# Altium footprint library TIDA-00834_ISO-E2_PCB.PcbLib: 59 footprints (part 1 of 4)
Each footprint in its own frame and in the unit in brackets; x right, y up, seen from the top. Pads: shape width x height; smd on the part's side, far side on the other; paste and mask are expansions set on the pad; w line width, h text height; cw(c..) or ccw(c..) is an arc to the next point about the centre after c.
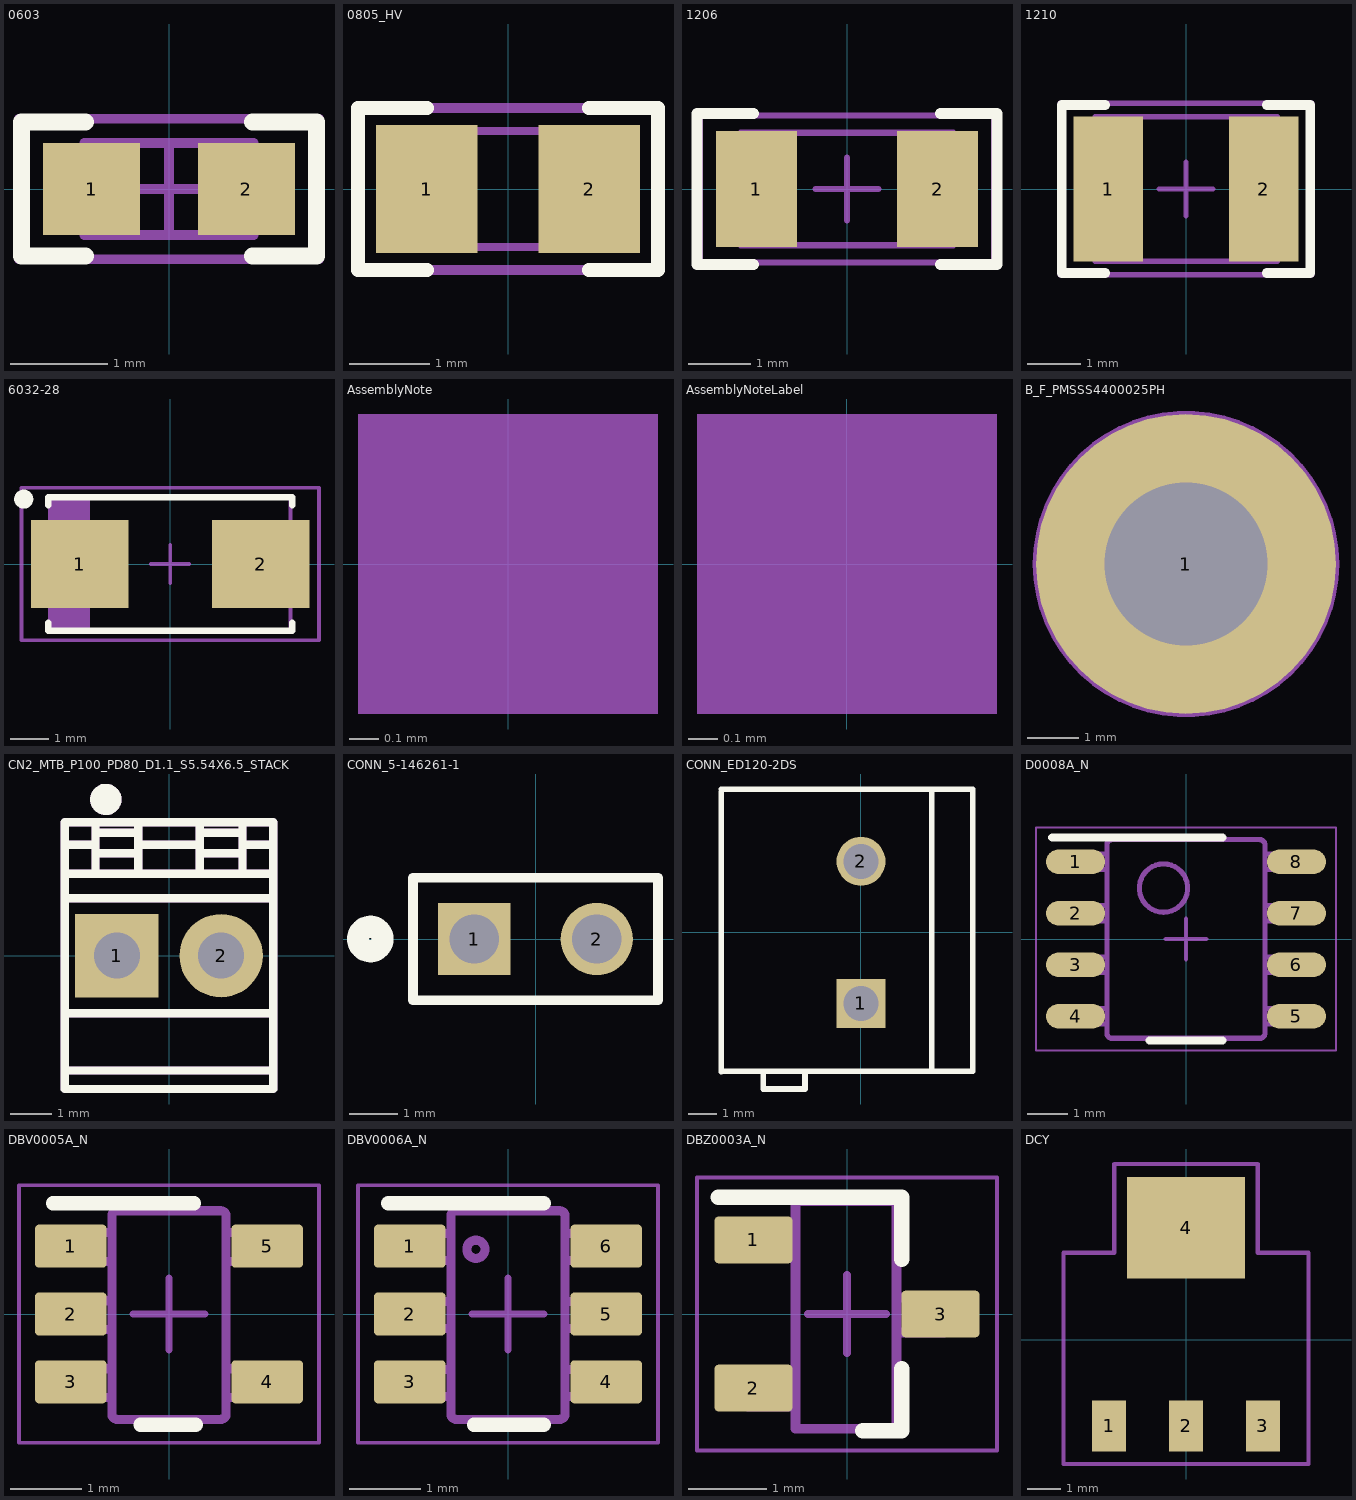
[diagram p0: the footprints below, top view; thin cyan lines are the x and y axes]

## 0603 [mm] "0603 from SM-752 data"
height 1
pads (2):
  rect 1x0.95 smd: 1(-0.8,0) 2(0.8,0)
Top Overlay:
  lines w0.178: -0.864,-0.691 -1.524,-0.691 -1.524,0.693 -0.864,0.693 ; 0.864,-0.691 1.524,-0.691 1.524,0.693 0.864,0.693
Mechanical 5:
  lines w0.1: -1.55,-0.725 -1.55,0.725 1.55,0.725 1.55,-0.725 -1.55,-0.725
  text ".Designator" at 1.143,0.254 h0.64
Mechanical 13:
  lines w0.1: -0.55,-0.475 -0.55,0.475 ; 0.55,-0.475 0.55,0.475 ; -0.875,-0.475 0.875,-0.475 0.875,0.475 -0.875,0.475 -0.875,-0.475
Mechanical 15:
  lines w0.1: -0.475,0 0.475,0 ; 0,-0.475 0,0.475 ; -1.55,-0.725 1.55,-0.725 1.55,0.725 -1.55,0.725 -1.55,-0.725
3D body: height 1, standoff 0, extent -0.874,-0.474 -0.551,0.474
3D body: height 1, standoff 0, extent -0.549,-0.474 0.549,0.474
3D body: height 1, standoff 0, extent 0.551,-0.474 0.874,0.474

## 0805_HV [mil] "0805 with 30mil clearance between pads"
height 57.09
pads (2):
  rect 50x63 smd: 1(-40,0) 2(40,0)
Top Overlay:
  lines w7: -40,-40 -74,-40 -74,0 -74,40 -40,40 ; 40,-40 74,-40 74,0 74,40 40,40
Mechanical 5:
  lines w5: -74,-40 74,-40 74,40 -74,40 -74,-40
  text ".Designator" at 42.09,10 h25
Mechanical 13:
  lines w3.94: -25.59,-28.54 -25.59,28.54 ; 25.59,-28.54 25.59,28.54 ; -43.31,-28.54 43.31,-28.54 43.31,28.54 -43.31,28.54 -43.31,-28.54
3D body: height 57.09, standoff 0, extent -43.29,-28.52 -25.61,28.52
3D body: height 57.09, standoff 0, extent -25.57,-28.52 25.57,28.52
3D body: height 57.09, standoff 0, extent 25.61,-28.52 43.29,28.52

## 1206 [mm] "1206 from SM-752 data"
height 1.35
pads (2):
  rect 1.3x1.85 smd: 1(-1.45,0) 2(1.45,0)
Top Overlay:
  lines w0.178: -1.5,-1.21 -2.4,-1.21 -2.4,1.21 -1.5,1.21 ; 1.5,-1.21 2.4,-1.21 2.4,1.21 1.5,1.21
Mechanical 5:
  lines w0.1: -1.7,-0.9 1.7,-0.9 1.7,0.9 -1.7,0.9 -1.7,-0.9
  text ".Designator" at -1.046,-0.381 h0.64
Mechanical 13:
  lines w0.1: -1.2,-0.9 -1.2,0.9 ; 1.2,-0.9 1.2,0.9 ; -1.7,-0.9 1.7,-0.9 1.7,0.9 -1.7,0.9 -1.7,-0.9
Mechanical 15:
  lines w0.1: -0.5,0 0.5,0 ; 0,-0.5 0,0.5 ; -2.35,-1.175 2.35,-1.175 2.35,1.175 -2.35,1.175 -2.35,-1.175
3D body: height 1.35, standoff 0, extent -1.699,-0.899 -1.201,0.899
3D body: height 1.35, standoff 0, extent -1.199,-0.899 1.199,0.899
3D body: height 1.35, standoff 0, extent 1.201,-0.899 1.699,0.899

## 1210 [mm] "1210 from SM-752 data"
height 1.35
pads (2):
  rect 1.3x2.7 smd: 1(-1.45,0) 2(1.45,0)
Top Overlay:
  lines w0.178: -1.511,-1.568 -2.316,-1.568 -2.316,1.568 -1.511,1.568 ; 1.511,-1.568 2.316,-1.568 2.316,1.568 1.511,1.568
Mechanical 5:
  lines w0.1: -1.7,-1.35 1.7,-1.35 1.7,1.35 -1.7,1.35 -1.7,-1.35
  text ".Designator" at 1.069,0.381 h0.64
Mechanical 13:
  lines w0.1: -1.2,-1.35 -1.2,1.35 ; 1.2,-1.35 1.2,1.35 ; -1.7,-1.35 -1.7,1.35 1.7,1.35 1.7,-1.35 -1.7,-1.35
Mechanical 15:
  lines w0.1: -0.5,0 0.5,0 ; 0,-0.5 0,0.5 ; -2.35,-1.6 -2.35,1.6 2.35,1.6 2.35,-1.6 -2.35,-1.6
3D body: height 1.35, standoff 0, extent -1.699,-1.349 -1.201,1.349
3D body: height 1.35, standoff 0, extent -1.199,-1.349 1.199,1.349
3D body: height 1.35, standoff 0, extent 1.201,-1.349 1.699,1.349

## 6032-28 [mm] "Medium Density IPC based on Vishay Sprague 293D datasheet."
height 2.8
pads (2):
  rect 2.55x2.3 smd: 1(-2.375,0) 2(2.375,0)
Top Overlay:
  circle w0.25: c-3.839,1.7 r0.125
  lines w0.178: -3.2,-1.539 -3.2,-1.75 3.2,-1.75 3.2,-1.539 ; -3.2,1.539 -3.2,1.75 3.2,1.75 3.2,1.539
Mechanical 5:
  rectangle: -3.15,-1.75 -2.15,1.75
  lines w0.1: -2.15,-1.75 -2.15,1.75 ; -3.15,-1.75 3.15,-1.75 3.15,1.75 -3.15,1.75 -3.15,-1.75
  text ".Designator" at 0.584,-0.965 h0.64
Mechanical 15:
  lines w0.1: -0.5,0 0.5,0 ; 0,-0.5 0,0.5 ; -3.9,-2 -3.9,2 3.9,2 3.9,-2 -3.9,-2
3D body: height 2.8, standoff 2.8, extent -3.149,-1.749 -2.151,1.749
3D body: height 2.8, standoff 0, extent -3.15,-1.75 3.15,1.75

## AssemblyNote [mm] "Assembly Note"
Mechanical 5:
  rectangle: -0.508,-0.508 0.508,0.508
  text ".Designator" at -4.191,-0.508 h0.76
  text ".Comment" at 1.143,-0.508 h0.76

## AssemblyNoteLabel [mm] "Assembly Note for PCB Labels"
Mechanical 5:
  rectangle: -0.508,-0.508 0.508,0.508
  text ".Designator" at -4.191,-0.508 h0.76
  text "Install label in silkscreened box after final wash.  Text shall be 8 pt font.  Text shall be per the Label Table in the PDF schematic." at 1.143,-0.508 h0.76

## B_F_PMSSS4400025PH [mil] "MACHINE SCREW PAN PHILLIPS 4-40"
height 82.68
pads (1):
  round 230 hole 125: 1(-5340,-4011)
Mechanical 5:
  circle w5: c-5340,-4011 r115
  text ".Designator" at -5380,-4036.85 h30
3D body "PMSSS 440 0025 PH.stp": height 79.21, standoff -248.03, extent -5449.5,-4120.49 -5230.5,-3901.49

## CN2_MTB_P100_PD80_D1.1_S5.54X6.5_STACK [mil]
height 118.11
pads (2):
  rect 80x80 / inner round 80 / far side rect 80x80 hole 44: 1(-50,0)
  round 80 hole 44: 2(50,0)
Top Overlay:
  circle w10: c-60.63,149.95 r5
  circle w10: c-60.63,149.95 r10
  lines w8: -100,-110.24 100,-110.24 ; -100,-55.12 100,-55.12 ; -100,55.12 100,55.12 ; -100,78.74 100,78.74 ; -100,106.3 -70.87,106.3 ; -70.47,78.74 -70.47,127.95 ; -70.47,98.43 -31.5,98.43 ; -70.47,118.11 -31.5,118.11 ; -29.53,78.74 -29.53,127.95 ; -27.56,106.3 27.56,106.3 ; 29.53,78.74 29.53,127.95 ; 31.5,98.43 66.93,98.43 ; 31.5,118.11 66.93,118.11 ; 70.47,78.74 70.47,127.95 ; 70.87,106.3 100,106.3 ; -100,-127.95 -100,127.95 100,127.95 100,-127.95 -100,-127.95
Mechanical 5:
  circle w10: c-60.63,149.95 r10
  circle w10: c-60.63,149.95 r5
  lines w8: -100,-110.24 100,-110.24 ; -100,-55.12 100,-55.12 ; -100,55.12 100,55.12 ; -100,78.74 100,78.74 ; -100,106.3 -70.87,106.3 ; -70.47,78.74 -70.47,127.95 ; -70.47,98.43 -31.5,98.43 ; -70.47,118.11 -31.5,118.11 ; -29.53,78.74 -29.53,127.95 ; -27.56,106.3 27.56,106.3 ; 29.53,78.74 29.53,127.95 ; 31.5,98.43 66.93,98.43 ; 31.5,118.11 66.93,118.11 ; 70.47,78.74 70.47,127.95 ; 70.87,106.3 100,106.3 ; -100,-127.95 100,-127.95 100,127.95 -100,127.95 -100,-127.95
  text ".designator" at -28,-10.95 h25

## CONN_5-146261-1 [mm] "Sullins"
height 8.21
pads (2):
  rect 1.5x1.5 hole 1.02: 1(-1.27,0)
  round 1.5 hole 1.02: 2(1.27,0)
Top Overlay:
  circle w0.457: c-3.429,0 r0.254
  lines w0.203: -2.54,-1.27 -2.54,1.27 2.54,1.27 2.54,-1.27 -2.54,-1.27
Mechanical 5:
  lines w0.076: -2.515,-1.27 2.515,-1.27 2.515,1.27 -2.515,1.27 -2.515,-1.27
  text ".Designator" at -1.016,-0.127 h0.64
3D body: height 10.87, standoff -2.67, extent 0.953,-0.317 1.588,0.318
3D body: height 10.87, standoff -2.67, extent -1.587,-0.317 -0.952,0.318
3D body: height 2.36, standoff 0, extent -2.514,-1.269 2.514,1.269

## CONN_ED120-2DS [mm] "ONSHORE"
height 13
pads (2):
  rect 1.75x1.75 hole 1.25: 1(0,-2.54)
  round 1.75 hole 1.25: 2(0,2.54)
Top Overlay:
  lines w0.2: -5,-4.985 -5,5.015 ; -5,-4.96 4,-4.96 ; -5,5.115 4,5.115 4,-4.885 ; -3.5,-4.96 -3.5,-5.6 -2,-5.6 -2,-4.96 ; 2.525,-4.95 2.525,5.05
Mechanical 5:
  lines w0.1: -5,-4.96 4,-4.96 ; -5,-4.885 -5,5.115 4,5.115 4,-4.885 ; -3.5,-4.96 -3.5,-5.6 -2,-5.6 -2,-4.96 ; 2.525,-4.875 2.525,5.125
  text ".Designator" at -1.803,-0.301 h0.64
3D body: height 13, standoff 0, extent -3.5,-5.6 -2,-4.925
3D body: height 5.7, standoff 4.3, extent -0.875,-3.204 4.125,-1.81
3D body: height 5.7, standoff 4.3, extent -0.85,1.846 4.15,3.24
3D body: height 13.1, standoff -2.5, extent -0.496,2.041 0.5,3.039
3D body: height 13.1, standoff -2.5, extent -0.496,-3.039 0.5,-2.041
3D body: height 13, standoff 0, extent -5,-4.985 4,5.115

## D0008A_N [mm] "SOIC, 8-Leads, Body 4.9x3.9mm, Pitch 1.27mm, IPC Medium Density"
height 1.75
pads (8):
  oval 1.45x0.6 smd: 1(-2.725,1.905) 2(-2.725,0.635) 3(-2.725,-0.635) 4(-2.725,-1.905) 5(2.725,-1.905) 6(2.725,-0.635) 7(2.725,0.635) 8(2.725,1.905)
Top Overlay:
  lines w0.2: -3.3,2.5 0.9,2.5 ; -0.9,-2.5 0.9,-2.5
Mechanical 5:
  lines w0.127: -2.375,-2.095 -2.375,-1.715 ; -2.375,-2.095 -2.589,-2.095 -3.002,-2.095 -3.002,-1.715 -2.589,-1.715 -2.375,-1.715 ; -2.375,-2.095 -1.995,-2.095 -1.952,-2.095 -1.952,-1.715 -1.995,-1.715 -2.375,-1.715 ; -2.375,-0.825 -2.375,-0.445 ; -2.375,-0.825 -2.589,-0.825 -3.002,-0.825 -3.002,-0.445 -2.589,-0.445 -2.375,-0.445 ; -2.375,-0.825 -1.995,-0.825 -1.952,-0.825 -1.952,-0.445 -1.995,-0.445 -2.375,-0.445 ; -2.375,0.445 -2.375,0.825 ; -2.375,0.445 -2.589,0.445 -3.002,0.445 -3.002,0.825 -2.589,0.825 -2.375,0.825 ; -2.375,0.445 -1.995,0.445 -1.952,0.445 -1.952,0.825 -1.995,0.825 -2.375,0.825 ; -2.375,1.715 -2.375,2.095 ; -2.375,1.715 -2.589,1.715 -3.002,1.715 -3.002,2.095 -2.589,2.095 -2.375,2.095 ; -2.375,1.715 -1.995,1.715 -1.952,1.715 -1.952,2.095 -1.995,2.095 -2.375,2.095 ; -0.332,-2.45 -0.182,-2.45 ; -0.332,-2.45 -0.182,-2.45 ; -0.332,-2.45 -1.825,-2.45 -1.826,-2.45 cw(c-1.825,-2.323) -1.952,-2.324 -1.952,-2.323 -1.952,2.323 -1.952,2.324 cw(c-1.825,2.323) -1.826,2.45 -1.825,2.45 -0.332,2.45 ; -0.332,2.45 -0.182,2.45 ; -0.332,2.45 -0.182,2.45 ; -0.182,-2.45 0.178,-2.45 ; -0.182,2.45 0.178,2.45 ; 0.178,-2.45 0.328,-2.45 ; 0.178,-2.45 0.328,-2.45 ; 0.178,2.45 0.328,2.45 ; 0.178,2.45 0.328,2.45 ; 0.328,-2.45 1.821,-2.45 1.822,-2.45 ccw(c1.821,-2.323) 1.948,-2.324 1.948,-2.323 1.948,2.323 1.948,2.324 ccw(c1.821,2.323) 1.822,2.45 1.821,2.45 0.328,2.45 ; 2.371,-2.095 2.371,-1.715 ; 2.371,-2.095 1.991,-2.095 1.948,-2.095 1.948,-1.715 1.991,-1.715 2.371,-1.715 ; 2.371,-2.095 2.585,-2.095 2.998,-2.095 2.998,-1.715 2.585,-1.715 2.371,-1.715 ; 2.371,-0.825 2.371,-0.445 ; 2.371,-0.825 1.991,-0.825 1.948,-0.825 1.948,-0.445 1.991,-0.445 2.371,-0.445 ; 2.371,-0.825 2.585,-0.825 2.998,-0.825 2.998,-0.445 2.585,-0.445 2.371,-0.445 ; 2.371,0.445 2.371,0.825 ; 2.371,0.445 1.991,0.445 1.948,0.445 1.948,0.825 1.991,0.825 2.371,0.825 ; 2.371,0.445 2.585,0.445 2.998,0.445 2.998,0.825 2.585,0.825 2.371,0.825 ; 2.371,1.715 2.371,2.095 ; 2.371,1.715 1.991,1.715 1.948,1.715 1.948,2.095 1.991,2.095 2.371,2.095 ; 2.371,1.715 2.585,1.715 2.998,1.715 2.998,2.095 2.585,2.095 2.371,2.095 ; -0.555,0.659 ccw(c-0.555,1.256) -0.555,1.853 ccw(c-0.555,1.256) -0.555,0.659
  text ".Designator" at 0.914,-0.056 h0.64
Mechanical 15:
  lines w0.05: -3.7,-2.75 -3.7,2.75 3.7,2.75 3.7,-2.75 -3.7,-2.75
  lines w0.1: -0.5,0 0.5,0 ; 0,-0.5 0,0.5
3D body "D0008A.stp": height 1.63, standoff 0, extent -3,-2.45 3,2.45

## DBV0005A_N [mm] "SOT23, 5-Leads, Body 2.9x1.6mm, Pitch 0.95mm, Lead Span 2.8mm, IPC Medium Density"
height 1.45
pads (5):
  rrect17% 1x0.6 smd: 1(-1.375,0.95) 2(-1.375,0) 3(-1.375,-0.95) 4(1.375,-0.95) 5(1.375,0.95)
Top Overlay:
  lines w0.2: -1.625,1.55 0.35,1.55 ; -0.4,-1.55 0.375,-1.55
Mechanical 5:
  lines w0.127: -0.801,1.371 cw(c-0.725,1.37) -0.725,1.446 ; -0.801,1.37 -0.801,-1.399 -0.801,-1.4 ccw(c-0.725,-1.399) -0.725,-1.475 ; -0.801,1.37 -0.801,1.371 ; -0.725,-1.475 -0.725,-1.475 ; -0.725,-1.475 0.723,-1.475 0.724,-1.475 ccw(c0.723,-1.399) 0.799,-1.4 0.799,-1.399 0.799,1.37 ; -0.725,1.446 0.723,1.446 0.724,1.446 cw(c0.723,1.37) 0.799,1.371 ; -0.725,1.446 -0.725,1.446 ; 0.799,1.37 0.799,1.371 ; -1.423,-1.167 -1.199,-1.167 -1.105,-1.167 -1.088,-1.167 -0.835,-1.167 -0.801,-1.167 -0.801,-0.767 -0.835,-0.767 -1.088,-0.767 -1.105,-0.767 -1.199,-0.767 -1.423,-0.767 -1.423,-1.167 ; -1.423,-0.215 -1.199,-0.215 -1.105,-0.215 -1.088,-0.215 -0.835,-0.215 -0.801,-0.215 -0.801,0.186 -0.835,0.186 -1.088,0.186 -1.105,0.186 -1.199,0.186 -1.423,0.186 -1.423,-0.215 ; -1.423,0.738 -1.199,0.738 -1.105,0.738 -1.088,0.738 -0.835,0.738 -0.801,0.738 -0.801,1.138 -0.835,1.138 -1.088,1.138 -1.105,1.138 -1.199,1.138 -1.423,1.138 -1.423,0.738 ; 0.799,-1.167 0.799,-0.767 0.834,-0.767 1.087,-0.767 1.103,-0.767 1.198,-0.767 1.422,-0.767 1.422,-1.167 1.198,-1.167 1.103,-1.167 1.087,-1.167 0.834,-1.167 0.799,-1.167 ; 0.799,0.738 0.799,1.138 0.834,1.138 1.087,1.138 1.103,1.138 1.198,1.138 1.422,1.138 1.422,0.738 1.198,0.738 1.103,0.738 1.087,0.738 0.834,0.738 0.799,0.738
  text ".Designator" at 0.33,-0.914 h0.64
Mechanical 15:
  lines w0.05: -2.1,-1.8 2.1,-1.8 2.1,1.8 -2.1,1.8 -2.1,-1.8
  lines w0.1: -0.5,0 0.5,0 ; 0,-0.5 0,0.5
3D body "DBV0005A.stp": height 1.09, standoff 0, extent -1.422,-1.46 1.422,1.461

## DBV0006A_N [mm] "SOT23, 6-Leads, Body 2.9x1.6mm, Pitch 0.95mm, Lead Span 2.8mm, IPC Medium Density"
height 1.45
pads (6):
  rrect17% 1x0.6 smd: 1(-1.375,0.95) 2(-1.375,0) 3(-1.375,-0.95) 4(1.375,-0.95) 5(1.375,0) 6(1.375,0.95)
Top Overlay:
  lines w0.2: -1.675,1.55 0.5,1.55 ; -0.475,-1.55 0.5,-1.55
Mechanical 5:
  lines w0.127: 0.724,-1.475 ccw(c0.723,-1.399) 0.8,-1.399 0.8,1.37 ccw(c0.723,1.37) 0.724,1.446 ; 0.723,-1.475 -0.724,-1.475 -0.725,-1.475 cw(c-0.724,-1.399) -0.801,-1.399 -0.801,1.37 cw(c-0.724,1.37) -0.725,1.446 -0.724,1.446 0.723,1.446 ; 0.723,-1.475 0.724,-1.475 ; 0.723,1.446 0.724,1.446 ; -1.423,-1.154 -1.423,-0.78 -1.206,-0.78 -1.113,-0.78 -1.081,-0.78 -0.828,-0.78 -0.801,-0.78 -0.801,-1.154 -0.828,-1.154 -1.081,-1.154 -1.113,-1.154 -1.206,-1.154 -1.423,-1.154 ; -1.423,-0.202 -1.423,0.173 -1.206,0.173 -1.113,0.173 -1.081,0.173 -0.828,0.173 -0.801,0.173 -0.801,-0.202 -0.828,-0.202 -1.081,-0.202 -1.113,-0.202 -1.206,-0.202 -1.423,-0.202 ; -1.423,0.751 -1.423,1.125 -1.206,1.125 -1.113,1.125 -1.081,1.125 -0.828,1.125 -0.801,1.125 -0.801,0.751 -0.828,0.751 -1.081,0.751 -1.113,0.751 -1.206,0.751 -1.423,0.751 ; -0.577,0.906 ccw(c-0.45,0.906) -0.323,0.906 ccw(c-0.45,0.906) -0.577,0.906 ; 0.8,-1.154 0.8,-0.78 0.827,-0.78 1.08,-0.78 1.112,-0.78 1.205,-0.78 1.422,-0.78 1.422,-1.154 1.205,-1.154 1.112,-1.154 1.08,-1.154 0.827,-1.154 0.8,-1.154 ; 0.8,-0.202 0.8,0.173 0.827,0.173 1.08,0.173 1.112,0.173 1.205,0.173 1.422,0.173 1.422,-0.202 1.205,-0.202 1.112,-0.202 1.08,-0.202 0.827,-0.202 0.8,-0.202 ; 0.8,0.751 0.8,1.125 0.827,1.125 1.08,1.125 1.112,1.125 1.205,1.125 1.422,1.125 1.422,0.751 1.205,0.751 1.112,0.751 1.08,0.751 0.827,0.751 0.8,0.751
  text ".Designator" at 0.33,-1.219 h0.64
Mechanical 15:
  lines w0.05: -2.1,-1.8 -2.1,1.8 2.1,1.8 2.1,-1.8 -2.1,-1.8
  lines w0.1: -0.5,0 0.5,0 ; 0,-0.5 0,0.5
3D body "DBV0006A.stp": height 1.12, standoff 0, extent -1.422,-1.461 1.423,1.46

## DBZ0003A_N [mm] "SOT23, 3-Leads, Body 2.9x1.3mm, Pitch 0.95mm, Lead Span 2.4mm, IPC Medium Density"
height 1.12
pads (3):
  rrect17% 1x0.6 smd: 1(-1.2,0.95) 2(-1.2,-0.95) 3(1.2,0)
Top Overlay:
  lines w0.2: -1.651,1.5 0.7,1.5 0.7,0.7 ; 0.2,-1.5 0.7,-1.5 0.7,-0.7
Mechanical 5:
  lines w0.127: -1.27,-1.187 -1.27,-0.743 -1.063,-0.743 -1.005,-0.743 -0.814,-0.743 -0.66,-0.743 -0.66,-1.187 -0.814,-1.187 -1.005,-1.187 -1.063,-1.187 -1.27,-1.187 ; -1.27,0.718 -1.27,1.162 -1.063,1.162 -1.005,1.162 -0.814,1.162 -0.66,1.162 -0.66,0.718 -0.814,0.718 -1.005,0.718 -1.063,0.718 -1.27,0.718 ; -0.66,-1.473 -0.66,1.448 0.635,1.448 0.635,-1.473 -0.66,-1.473 ; 0.635,-0.235 0.789,-0.235 0.98,-0.235 1.037,-0.235 1.245,-0.235 1.245,0.21 1.037,0.21 0.98,0.21 0.789,0.21 0.635,0.21 0.635,-0.235
  text ".Designator" at -0.381,0.889 h0.64
Mechanical 15:
  lines w0.05: -1.925,-1.75 1.925,-1.75 1.925,1.75 -1.925,1.75 -1.925,-1.75
  lines w0.1: -0.5,0 0.5,0 ; 0,-0.5 0,0.5
3D body "DBZ0003A.stp": height 0.98, standoff 0, extent -1.257,-1.461 1.258,1.461

## DCY [mil]
pads (4):
  rect 40x60 smd: 1(-91,-102.2) 2(0,-102.2) 3(91,-102.2)
  rect 140x120 smd: 4(0,132.3)
Mechanical 5:
  lines w5: -145,-147.2 145,-147.2 145,102.8 85,102.8 85,207.8 -85,207.8 -85,102.8 -145,102.8 -145,-147.2
  text ".Designator" at -25,0 h25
